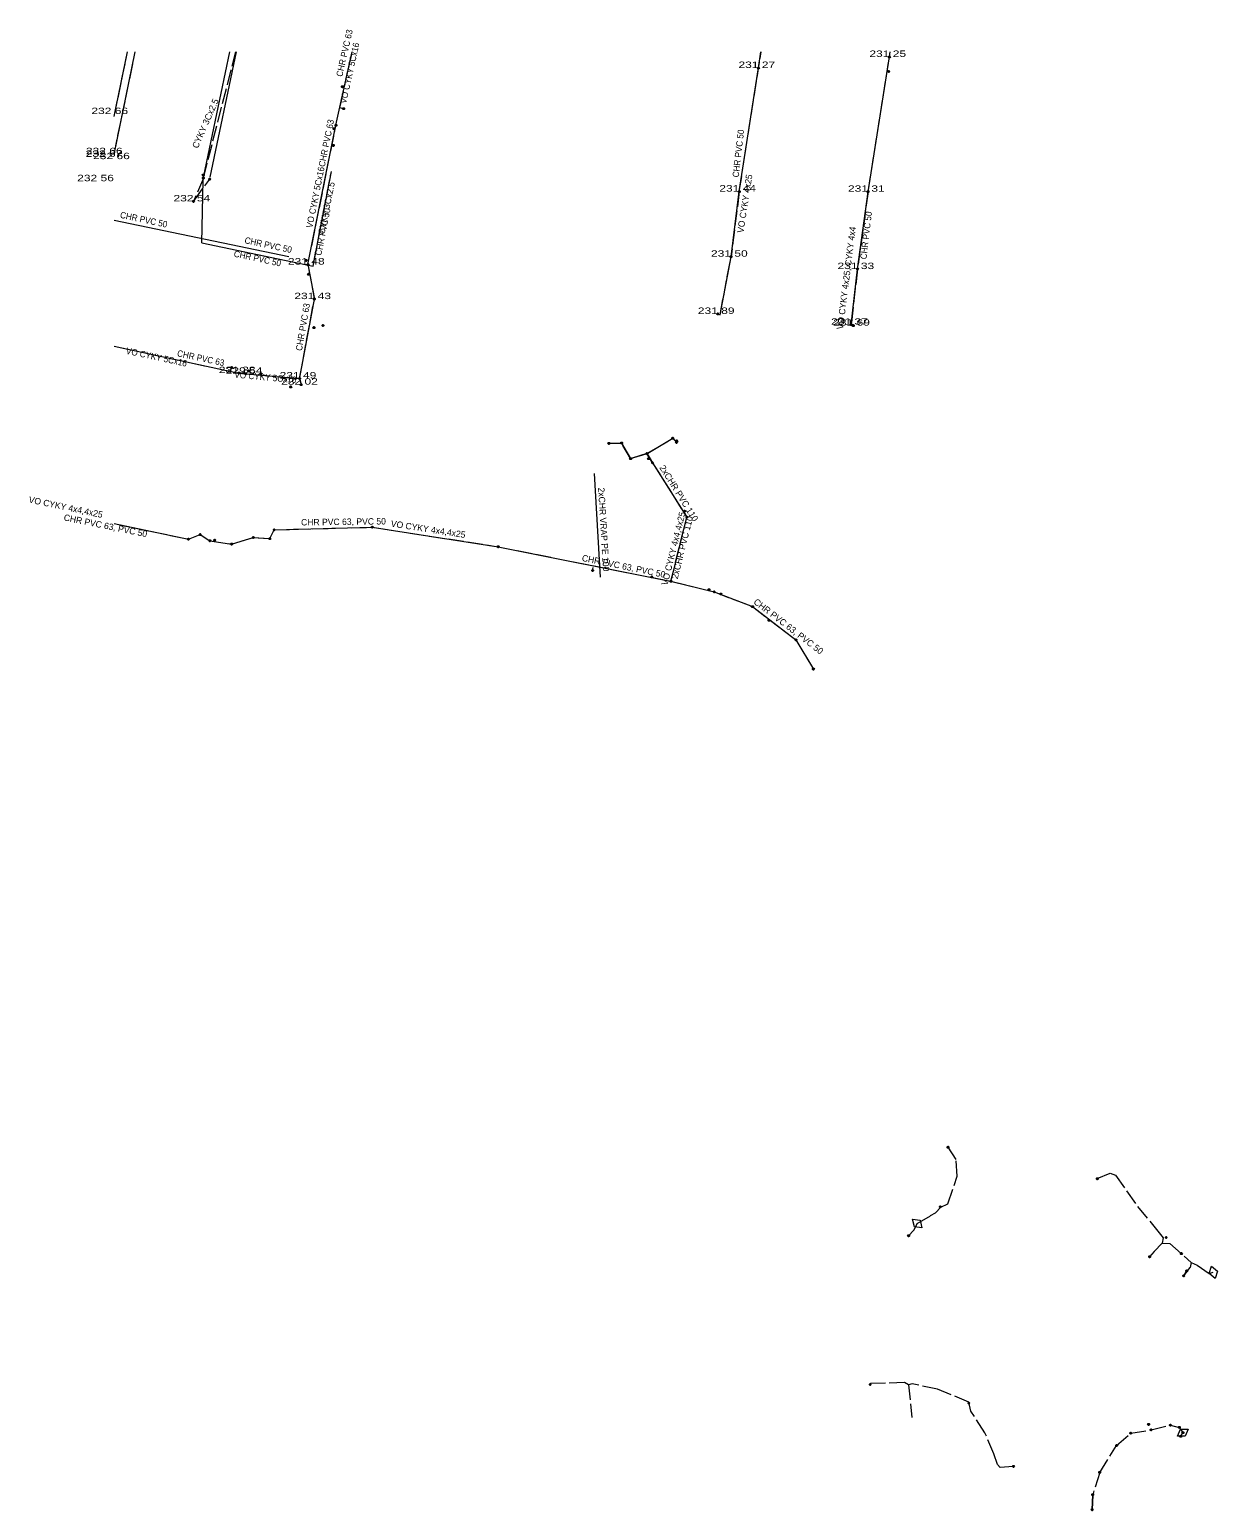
# Model space of a CAD drawing. Extents: x -642294 to -641980, y -1041631 to -1041422.
# Drawn here: x -642293.7 to -642154.8, y -1041595.4 to -1041422.3 of the extents above; entities that cross this region are included whole.
import ezdxf
from ezdxf.enums import TextEntityAlignment as Align

# ---------------------------------------------------------------- set-up
doc = ezdxf.new("R2010")
doc.units = 0
doc.header["$LTSCALE"] = 0.3
doc.header["$PDMODE"] = 32
doc.header["$PDSIZE"] = 0.15
doc.linetypes.add('LONG_DASHED', pattern=[7.5, 6, -1.5])
for name, color, linetype in [('1', 7, 'Continuous'), ('16', 7, 'Continuous'), ('20', 7, 'Continuous'), ('3', 7, 'Continuous')]:
    doc.layers.add(name, color=color, linetype=linetype)
for name, color, linetype, lineweight in [('10', 7, 'Continuous', 13), ('25', 7, 'Continuous', 13), ('30', 7, 'LONG_DASHED', 13), ('35', 7, 'LONG_DASHED', 13)]:
    doc.layers.add(name, color=color, linetype=linetype, lineweight=lineweight)

msp = doc.modelspace()

# ---------------------------------------------------------------- linework, layer by layer
at = {"layer": '1'}
for p in [(-642193.12, -1041425.54), (-642208.43, -1041426.83), (-642193.19, -1041427.25), (-642257.08, -1041429.03), (-642256.94, -1041431.59), (-642258.06, -1041433.93), (-642257.83, -1041433.53), (-642258.14, -1041435.88), (-642273.35, -1041439.35), (-642273.34, -1041439.7), (-642272.59, -1041439.83), (-642210.67, -1041441.28), (-642195.62, -1041441.3), (-642274.49, -1041442.43), (-642261.32, -1041449.33), (-642261.11, -1041449.81), (-642211.64, -1041448.89), (-642196.85, -1041450.34), (-642261.03, -1041450.94), (-642260.36, -1041453.85), (-642260.41, -1041457.18), (-642259.36, -1041456.93), (-642213.18, -1041455.58), (-642197.59, -1041456.84), (-642197.35, -1041456.95), (-642270.02, -1041461.85), (-642268.01, -1041462.24), (-642269.19, -1041462.5), (-642268.38, -1041462.58), (-642266.59, -1041462.61), (-642263.12, -1041464.11), (-642262.08, -1041463.13), (-642261.9, -1041463.85), (-642225.92, -1041470.72), (-642224.44, -1041470.67), (-642218.45, -1041470.12), (-642218.02, -1041470.6), (-642217.99, -1041470.43), (-642223.38, -1041472.5), (-642221.47, -1041471.9), (-642221.28, -1041472.49), (-642220.82, -1041472.99), (-642217.07, -1041478.64), (-642216.8, -1041479.34), (-642273.71, -1041481.38), (-642265.06, -1041480.82), (-642253.59, -1041480.51), (-642275.09, -1041481.91), (-642272.58, -1041482.09), (-642272.01, -1041482.03), (-642270.03, -1041482.48), (-642267.5, -1041481.72), (-642265.57, -1041481.85), (-642238.87, -1041482.79), (-642227.83, -1041485.57), (-642220.9, -1041486.32), (-642218.66, -1041486.83), (-642214.22, -1041487.81), (-642213.61, -1041488.07), (-642212.83, -1041488.32), (-642209.12, -1041489.8), (-642207.2, -1041491.4), (-642204.05, -1041493.68), (-642202.01, -1041497.09), (-642186.26, -1041552.99), (-642168.81, -1041556.67), (-642187.17, -1041559.95), (-642190.88, -1041563.33), (-642160.76, -1041563.54), (-642162.69, -1041565.79), (-642158.98, -1041565.42), (-642158.7, -1041568.02), (-642158.36, -1041567.45), (-642195.37, -1041580.72), (-642183.83, -1041582.9), (-642164.9, -1041586.41), (-642162.81, -1041585.38), (-642162.53, -1041586.02), (-642160.26, -1041585.47), (-642159.22, -1041585.73), (-642159.05, -1041586.77), (-642158.8, -1041586.35), (-642166.56, -1041587.85), (-642178.61, -1041590.29), (-642168.53, -1041591), (-642169.35, -1041593.61), (-642169.41, -1041595.36)]:
    msp.add_point(p, dxfattribs=at)
at = {"layer": '10'}
for points in [[(-642190.204, -1041562.272), (-642190.426, -1041561.399), (-642189.534, -1041561.529), (-642189.312, -1041562.403)], [(-642154.769, -1041567.464), (-642155.048, -1041568.321), (-642155.732, -1041567.734), (-642155.452, -1041566.877)], [(-642158.519, -1041586.763), (-642159.42, -1041586.77), (-642159.08, -1041585.935), (-642158.178, -1041585.929)]]:
    msp.add_lwpolyline(points, close=True, dxfattribs=at)
at = {"layer": '25'}
for p, q in [((-642283.775, -1041436.936), (-642281.298, -1041424.94)), ((-642283.775, -1041432.519), (-642282.192, -1041424.94)), ((-642273.285, -1041439.455), (-642270.239, -1041424.94)), ((-642272.555, -1041439.585), (-642269.451, -1041424.94)), ((-642257.83, -1041433.53), (-642255.924, -1041424.94)), ((-642208.43, -1041426.83), (-642208.135, -1041424.94)), ((-642195.62, -1041441.3), (-642193.12, -1041425.54)), ((-642193.12, -1041425.54), (-642193.027, -1041424.94)), ((-642210.67, -1041441.28), (-642208.43, -1041426.83)), ((-642261.11, -1041449.81), (-642257.83, -1041433.53)), ((-642273.535, -1041447.275), (-642273.35, -1041439.95)), ((-642211.64, -1041448.89), (-642210.67, -1041441.28)), ((-642196.85, -1041450.34), (-642195.62, -1041441.3)), ((-642283.775, -1041444.606), (-642263.34, -1041448.85)), ((-642261.11, -1041449.81), (-642260.36, -1041453.85)), ((-642212.91, -1041455.675), (-642211.64, -1041448.89)), ((-642197.59, -1041456.84), (-642196.85, -1041450.34)), ((-642262.06, -1041463.015), (-642260.36, -1041453.85)), ((-642283.775, -1041459.364), (-642269.19, -1041462.5)), ((-642269.19, -1041462.5), (-642262.24, -1041463.115)), ((-642262.06, -1041463.22), (-642261.9, -1041463.85)), ((-642225.92, -1041470.72), (-642224.44, -1041470.67)), ((-642224.44, -1041470.67), (-642223.38, -1041472.5)), ((-642221.375, -1041471.845), (-642218.45, -1041470.12)), ((-642218.45, -1041470.12), (-642218.02, -1041470.6)), ((-642223.38, -1041472.5), (-642221.555, -1041471.93)), ((-642221.38, -1041472.055), (-642220.82, -1041472.99)), ((-642227.64, -1041474.24), (-642226.95, -1041486.35)), ((-642220.82, -1041472.99), (-642216.8, -1041479.34)), ((-642218.615, -1041486.64), (-642216.8, -1041479.34)), ((-642283.775, -1041480.086), (-642275.09, -1041481.91)), ((-642275.09, -1041481.91), (-642273.71, -1041481.38)), ((-642273.71, -1041481.38), (-642272.58, -1041482.09)), ((-642272.58, -1041482.09), (-642270.03, -1041482.48)), ((-642270.03, -1041482.48), (-642267.5, -1041481.72)), ((-642267.5, -1041481.72), (-642265.57, -1041481.85)), ((-642204.05, -1041493.68), (-642202.01, -1041497.09))]:
    msp.add_line(p, q, dxfattribs=at)
for points in [[(-642273.535, -1041447.275), (-642260.51, -1041450.005), (-642258.36, -1041438.95)], [(-642265.57, -1041481.85), (-642265.06, -1041480.82), (-642253.59, -1041480.51)], [(-642253.59, -1041480.51), (-642238.87, -1041482.79), (-642218.755, -1041486.815)], [(-642218.56, -1041486.855), (-642213.61, -1041488.07), (-642209.12, -1041489.8), (-642204.05, -1041493.68)]]:
    msp.add_lwpolyline(points, dxfattribs=at)
at = {"layer": '30'}
for p, q in [((-642158.7, -1041568.02), (-642158.36, -1041567.45)), ((-642159.05, -1041586.77), (-642158.8, -1041586.35))]:
    msp.add_line(p, q, dxfattribs=at)
msp.add_lwpolyline([(-642168.53, -1041591), (-642169.35, -1041593.61), (-642169.41, -1041595.36)], dxfattribs=at)
at = {"layer": '35'}
for p, q in [((-642283.775, -1041432.515), (-642282.19, -1041424.94)), ((-642283.775, -1041436.935), (-642281.296, -1041424.94)), ((-642273.34, -1041439.7), (-642269.532, -1041424.94)), ((-642257.83, -1041433.53), (-642255.924, -1041424.94)), ((-642210.67, -1041441.28), (-642208.125, -1041424.94)), ((-642195.62, -1041441.3), (-642193.12, -1041425.54)), ((-642193.12, -1041425.54), (-642193.027, -1041424.94)), ((-642256.94, -1041431.59), (-642257.38, -1041431.49)), ((-642261.11, -1041449.81), (-642257.83, -1041433.53)), ((-642273.34, -1041439.7), (-642274.49, -1041442.43)), ((-642274.49, -1041442.43), (-642272.59, -1041439.83)), ((-642259.75, -1041446.07), (-642258.36, -1041438.95)), ((-642210.67, -1041441.28), (-642211.64, -1041448.89)), ((-642195.62, -1041441.3), (-642196.85, -1041450.34)), ((-642260.51, -1041450.01), (-642259.75, -1041446.07)), ((-642261.11, -1041449.81), (-642260.36, -1041453.85)), ((-642262.08, -1041463.13), (-642260.36, -1041453.85)), ((-642283.775, -1041459.364), (-642269.19, -1041462.5)), ((-642269.19, -1041462.5), (-642262.08, -1041463.13)), ((-642262.08, -1041463.13), (-642261.9, -1041463.85)), ((-642220.82, -1041472.99), (-642216.8, -1041479.34)), ((-642218.66, -1041486.83), (-642216.8, -1041479.34)), ((-642283.775, -1041480.084), (-642275.09, -1041481.91)), ((-642265.06, -1041480.82), (-642253.59, -1041480.51)), ((-642227.83, -1041485.57), (-642227.76, -1041485.22)), ((-642158.699, -1041568.02), (-642157.95, -1041567.05)), ((-642157.83, -1041566.45), (-642157.95, -1041567.05)), ((-642190.87, -1041580.74), (-642190.49, -1041584.58)), ((-642162.53, -1041586.02), (-642160.26, -1041585.47)), ((-642160.26, -1041585.47), (-642159.22, -1041585.73)), ((-642159.22, -1041585.73), (-642158.8, -1041586.35)), ((-642169.41, -1041595.36), (-642169.35, -1041593.61))]:
    msp.add_line(p, q, dxfattribs=at)
for points in [[(-642213.18, -1041455.58), (-642212.91, -1041455.67), (-642211.64, -1041448.89)], [(-642196.85, -1041450.34), (-642197.59, -1041456.84), (-642197.35, -1041456.95)], [(-642220.82, -1041472.99), (-642221.47, -1041471.9), (-642223.38, -1041472.5), (-642224.44, -1041470.67), (-642225.92, -1041470.72)], [(-642221.47, -1041471.9), (-642218.45, -1041470.12), (-642218.02, -1041470.6)], [(-642275.09, -1041481.91), (-642273.71, -1041481.38), (-642272.58, -1041482.09)], [(-642272.58, -1041482.09), (-642270.03, -1041482.48), (-642267.5, -1041481.72), (-642265.57, -1041481.85), (-642265.06, -1041480.82)], [(-642253.59, -1041480.51), (-642238.87, -1041482.79), (-642218.66, -1041486.83)], [(-642218.66, -1041486.83), (-642213.61, -1041488.07), (-642209.12, -1041489.8), (-642204.05, -1041493.68), (-642202.01, -1041497.09)], [(-642190.93, -1041563.37), (-642190.23, -1041562.64), (-642189.87, -1041561.9), (-642188.31, -1041560.98), (-642187.72, -1041560.67), (-642187.12, -1041559.98), (-642186.28, -1041559.6), (-642185.19, -1041556.36), (-642185.32, -1041554.42), (-642186.26, -1041552.99)], [(-642168.84, -1041556.64), (-642167.3, -1041556.02), (-642166.67, -1041556.24), (-642164.11, -1041559.9), (-642162.22, -1041562.2), (-642161.1, -1041563.59), (-642161.24, -1041564.2), (-642162.16, -1041565.18), (-642162.69, -1041565.79)], [(-642161.24, -1041564.2), (-642160.34, -1041564.23), (-642157.83, -1041566.45), (-642157.13, -1041566.78), (-642155.75, -1041567.74), (-642155.25, -1041567.6)], [(-642178.64, -1041590.29), (-642180.16, -1041590.42), (-642180.47, -1041590.09), (-642180.91, -1041588.83), (-642181.95, -1041586.36), (-642183.6, -1041583.82), (-642183.82, -1041582.78), (-642187.49, -1041581.28), (-642190.45, -1041580.65), (-642190.87, -1041580.74), (-642191.34, -1041580.49), (-642195.35, -1041580.62)], [(-642168.53, -1041591), (-642166.56, -1041587.85), (-642164.9, -1041586.41), (-642162.53, -1041586.02)]]:
    msp.add_lwpolyline(points, dxfattribs=at)

# ---------------------------------------------------------------- texts
at = {"layer": '16', "width": 0.95}
for rotation, p in [(77.492, (-642256.649, -1041431.052)), (78.609, (-642260.598, -1041445.583)), (347.867, (-642282.436, -1041460.229)), (354.936, (-642269.734, -1041463.028))]:
    msp.add_text('VO CYKY 5Cx16', height=0.75, rotation=rotation, dxfattribs=at).set_placement(p)
at = {"layer": '16'}
for s, rotation, p in [('CYKY 3Cx2.5', 66.368, (-642273.996, -1041436.302)), ('VO CYKY 4x25', 81.188, (-642210.192, -1041446.159)), ('CYKY 3Cx2.5', 78.609, (-642259.179, -1041446.307)), ('VO CYKY 4x25, CYKY 4x4', 82.79, (-642198.544, -1041457.428)), ('VO CYKY 4x4,4x25', 348.13, (-642293.814, -1041477.624)), ('VO CYKY 4x4,4x25', 351.195, (-642251.457, -1041480.432)), ('VO CYKY 4x4,4x25', 76.054, (-642219.077, -1041487.368))]:
    msp.add_text(s, height=0.75, rotation=rotation, dxfattribs=at).set_placement(p)
at = {"layer": '20', "width": 0.95}
for s, rotation, p in [('CHR PVC 63', 77.319, (-642257.09, -1041427.91)), ('CHR PVC 63', 78.646, (-642259.15, -1041438.44)), ('CHR PVC 50', 83.38, (-642210.74, -1041439.65)), ('CHR PVC 50', 78.646, (-642259.56, -1041448.81)), ('CHR PVC 50', 348.02, (-642283.13, -1041444.34)), ('CHR PVC 50', 83.38, (-642195.8, -1041449.23)), ('CHR PVC 50', 348.02, (-642268.57, -1041447.31)), ('CHR PVC 50', 348.02, (-642269.83, -1041448.88)), ('CHR PVC 63', 80.248, (-642261.81, -1041459.94)), ('CHR PVC 63', 347.908, (-642276.46, -1041460.52))]:
    msp.add_text(s, height=0.75, rotation=rotation, dxfattribs=at).set_placement(p)
at = {"layer": '20'}
for s, rotation, p in [('2xCHR PVC 110', 302.047, (-642220.05, -1041473.55)), ('2xCHR VRAP PE 100', 273.452, (-642227.19, -1041475.9)), ('CHR PVC 63, PVC 50', 348.456, (-642289.71, -1041479.71)), ('CHR PVC 63, PVC 50', 0.692, (-642261.91, -1041480.31)), ('2xCHR PVC 110', 76.093, (-642217.88, -1041486.62)), ('CHR PVC 63, PVC 50', 348.456, (-642229.13, -1041484.45)), ('CHR PVC 63, PVC 50', 322.447, (-642209.08, -1041489.38))]:
    msp.add_text(s, height=0.75, rotation=rotation, dxfattribs=at).set_placement(p)
at = {"layer": '3', "width": 1.4}
for s, p in [('231 25 ', (-642193.12, -1041425.54)), ('231 27 ', (-642208.43, -1041426.83)), ('232 66 ', (-642284.09, -1041432.22)), ('232 66 ', (-642284.73, -1041436.91)), ('232 67 ', (-642284.76, -1041437.22)), ('232 66 ', (-642283.89, -1041437.49)), ('232 56 ', (-642285.75, -1041440.07)), ('231 44 ', (-642210.67, -1041441.28)), ('231 31 ', (-642195.62, -1041441.3)), ('232 54 ', (-642274.49, -1041442.43)), ('231 50 ', (-642211.64, -1041448.89)), ('231 48 ', (-642261.11, -1041449.81)), ('231 33 ', (-642196.85, -1041450.34)), ('231 43 ', (-642260.36, -1041453.85)), ('231 89 ', (-642213.18, -1041455.58)), ('231 37 ', (-642197.59, -1041456.84)), ('231 69 ', (-642197.35, -1041456.95)), ('231 38 ', (-642269.19, -1041462.5)), ('229 54 ', (-642268.38, -1041462.58)), ('231 49 ', (-642262.08, -1041463.13)), ('232 02 ', (-642261.9, -1041463.85))]:
    msp.add_text(s, height=0.75, dxfattribs=at).set_placement(p, align=Align.CENTER)

doc.saveas('drawing.dxf')
